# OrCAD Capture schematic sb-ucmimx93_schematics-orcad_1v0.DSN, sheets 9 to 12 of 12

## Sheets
9 11 Power: size A3; title: SB-UCMIMX93    08. Power
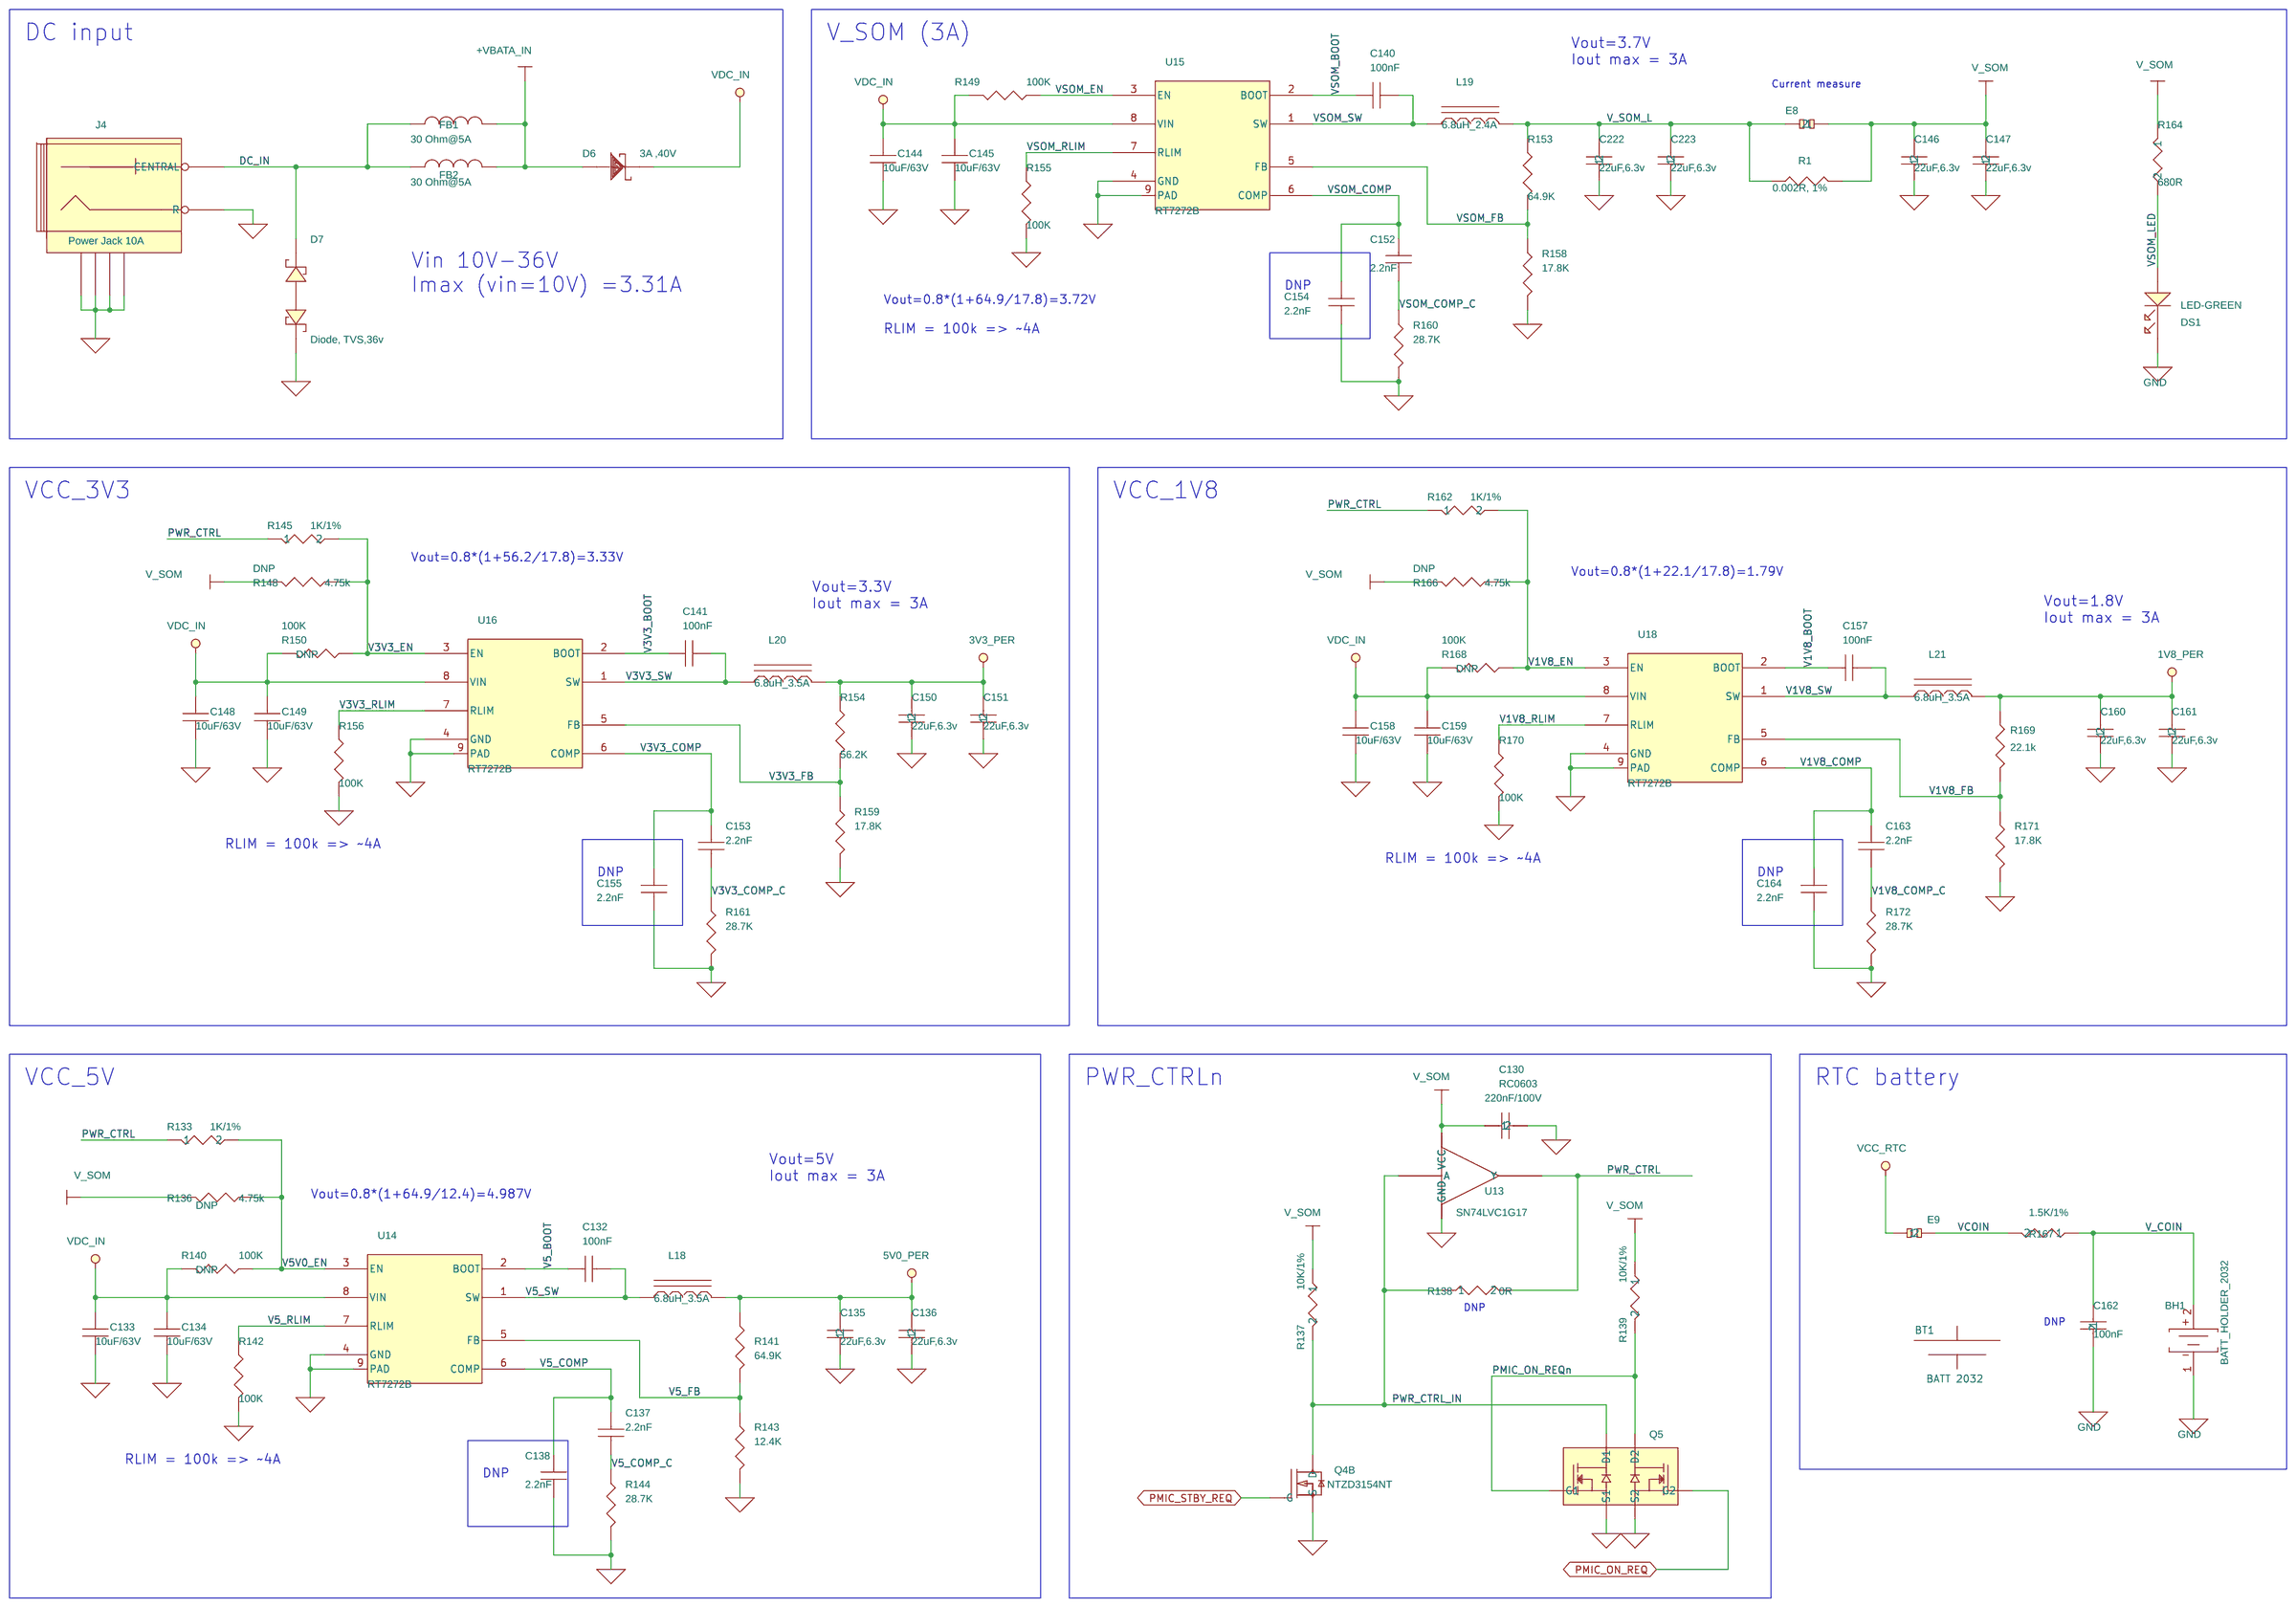
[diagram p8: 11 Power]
10 03 Ethernet and Expansion conn.: size A3; title: SB-UCMIMX93      03. Ethernet and Expansion connectors
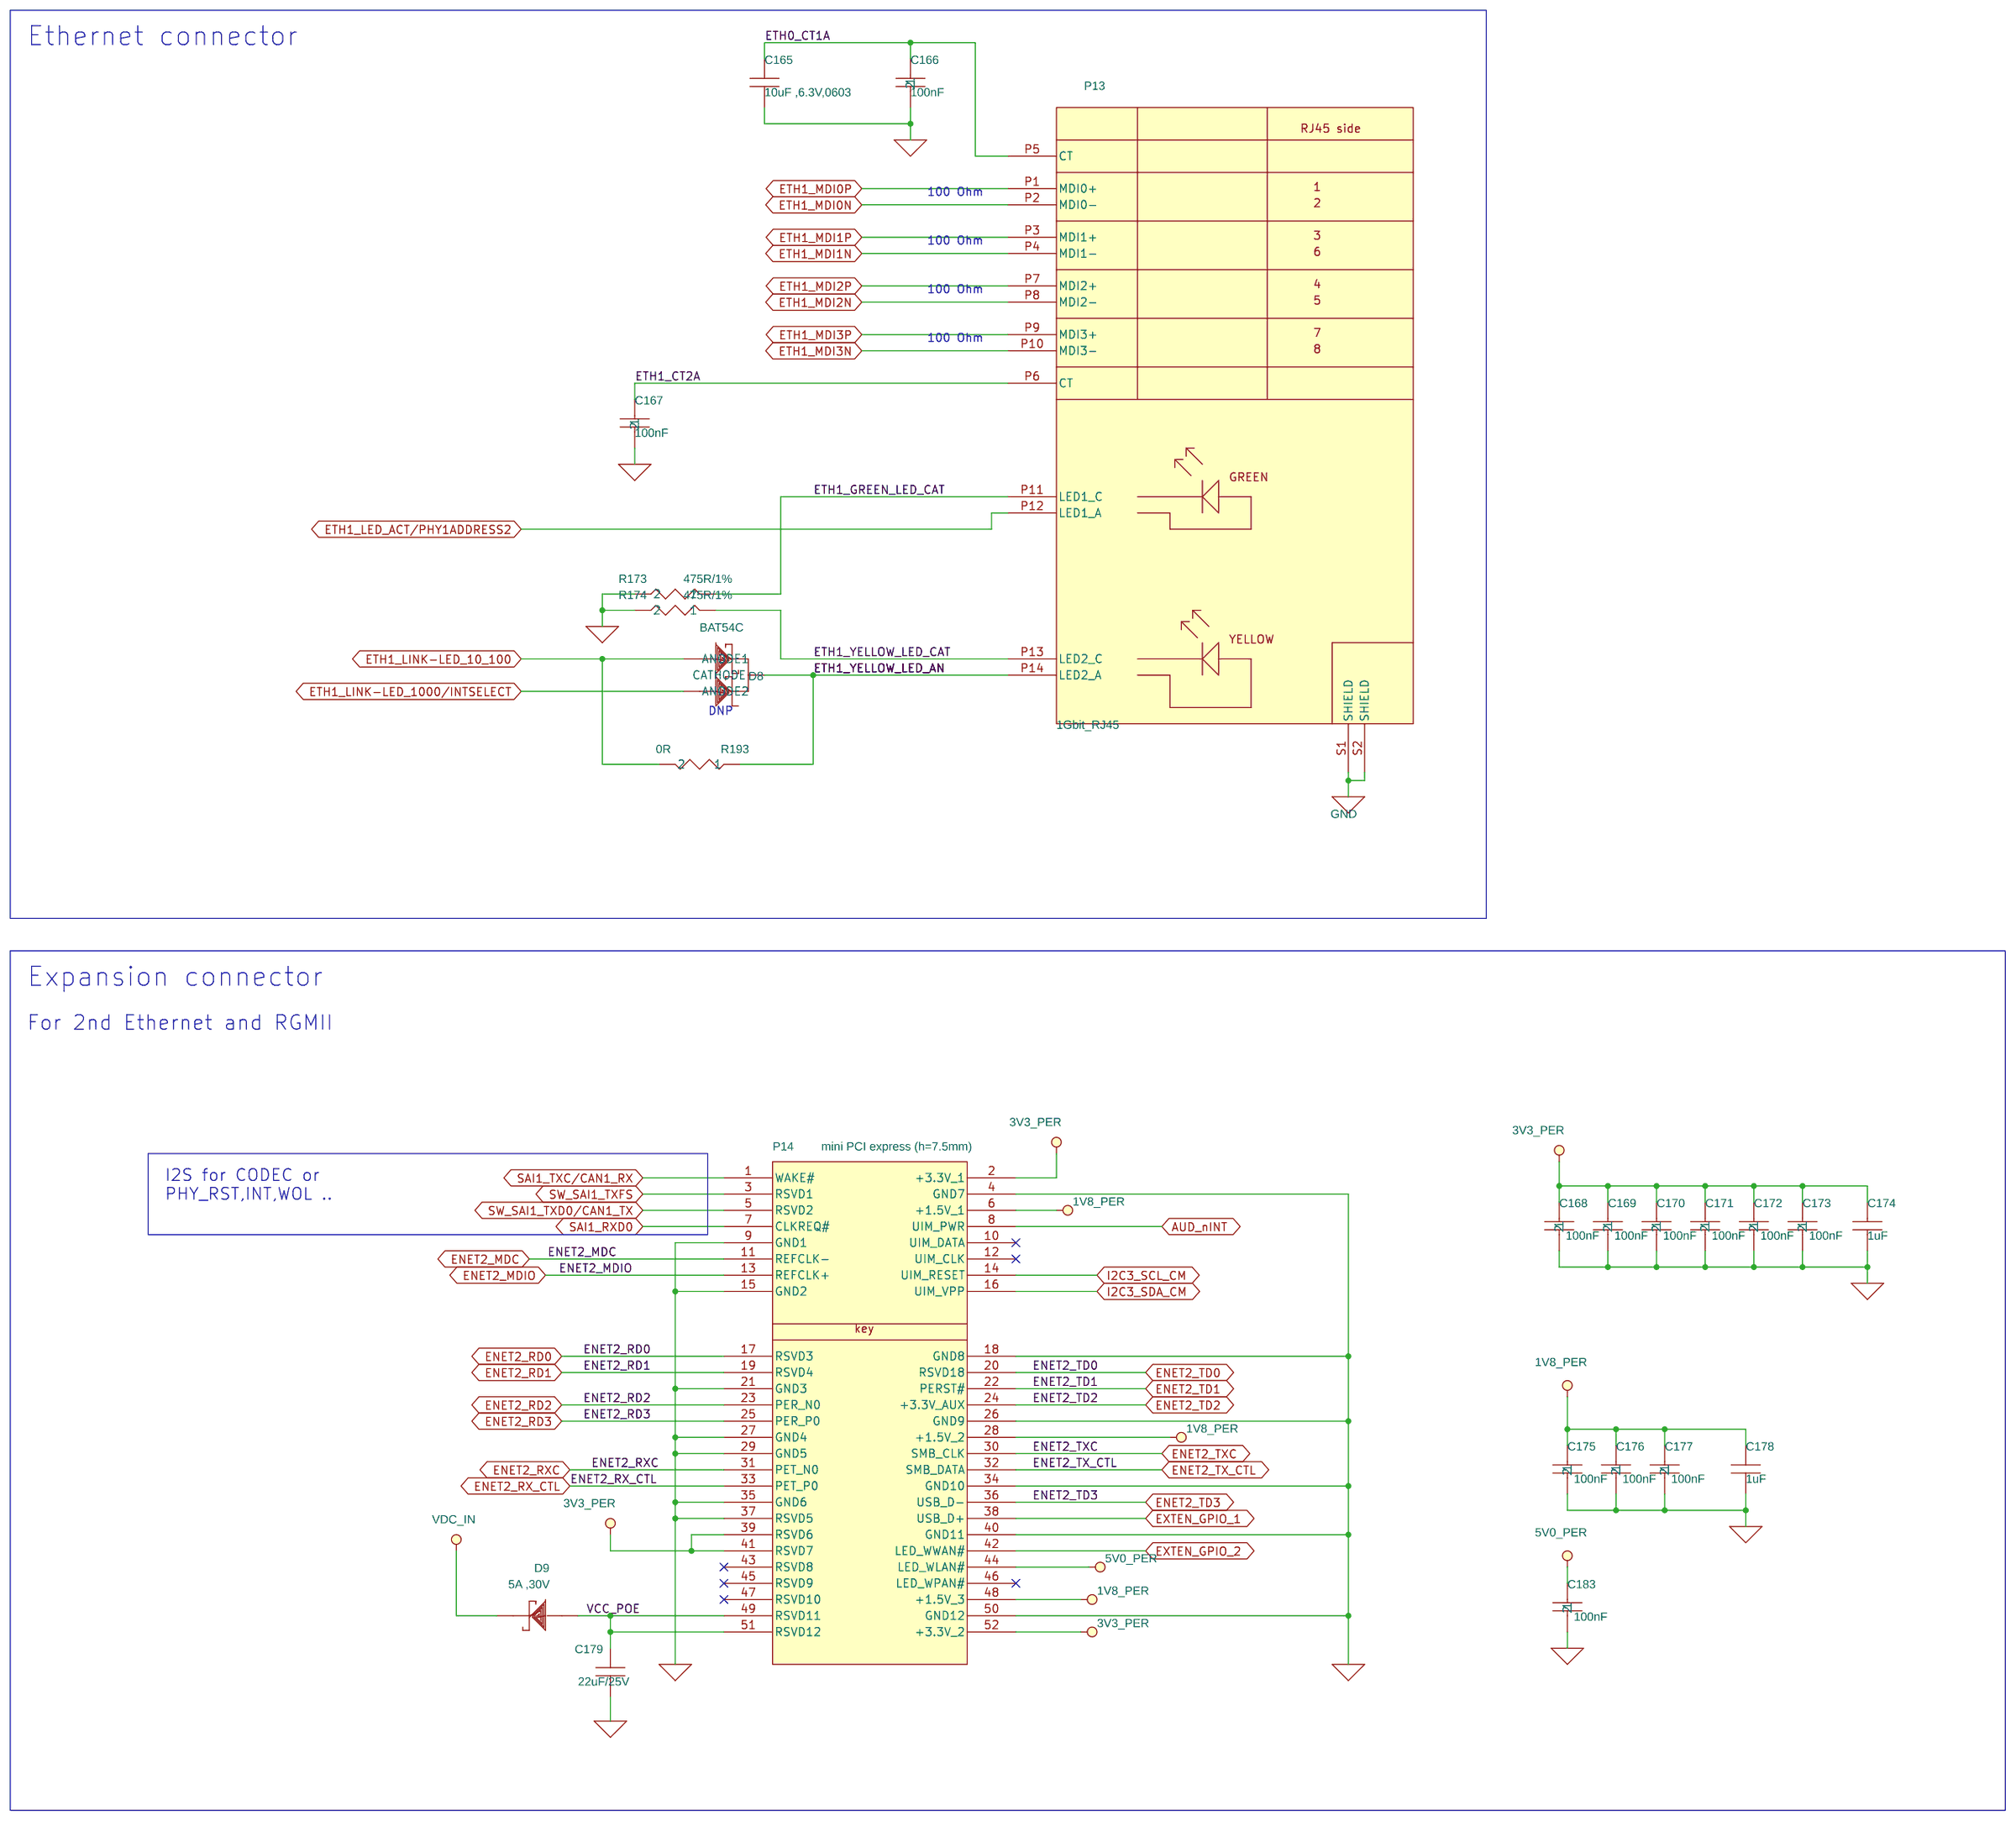
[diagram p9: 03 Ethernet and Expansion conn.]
11 10 Console, RS232, SD, miniPCIe: size A3; title: SB-UCMIMX93      10. Console, RS232, SD, miniPCIe
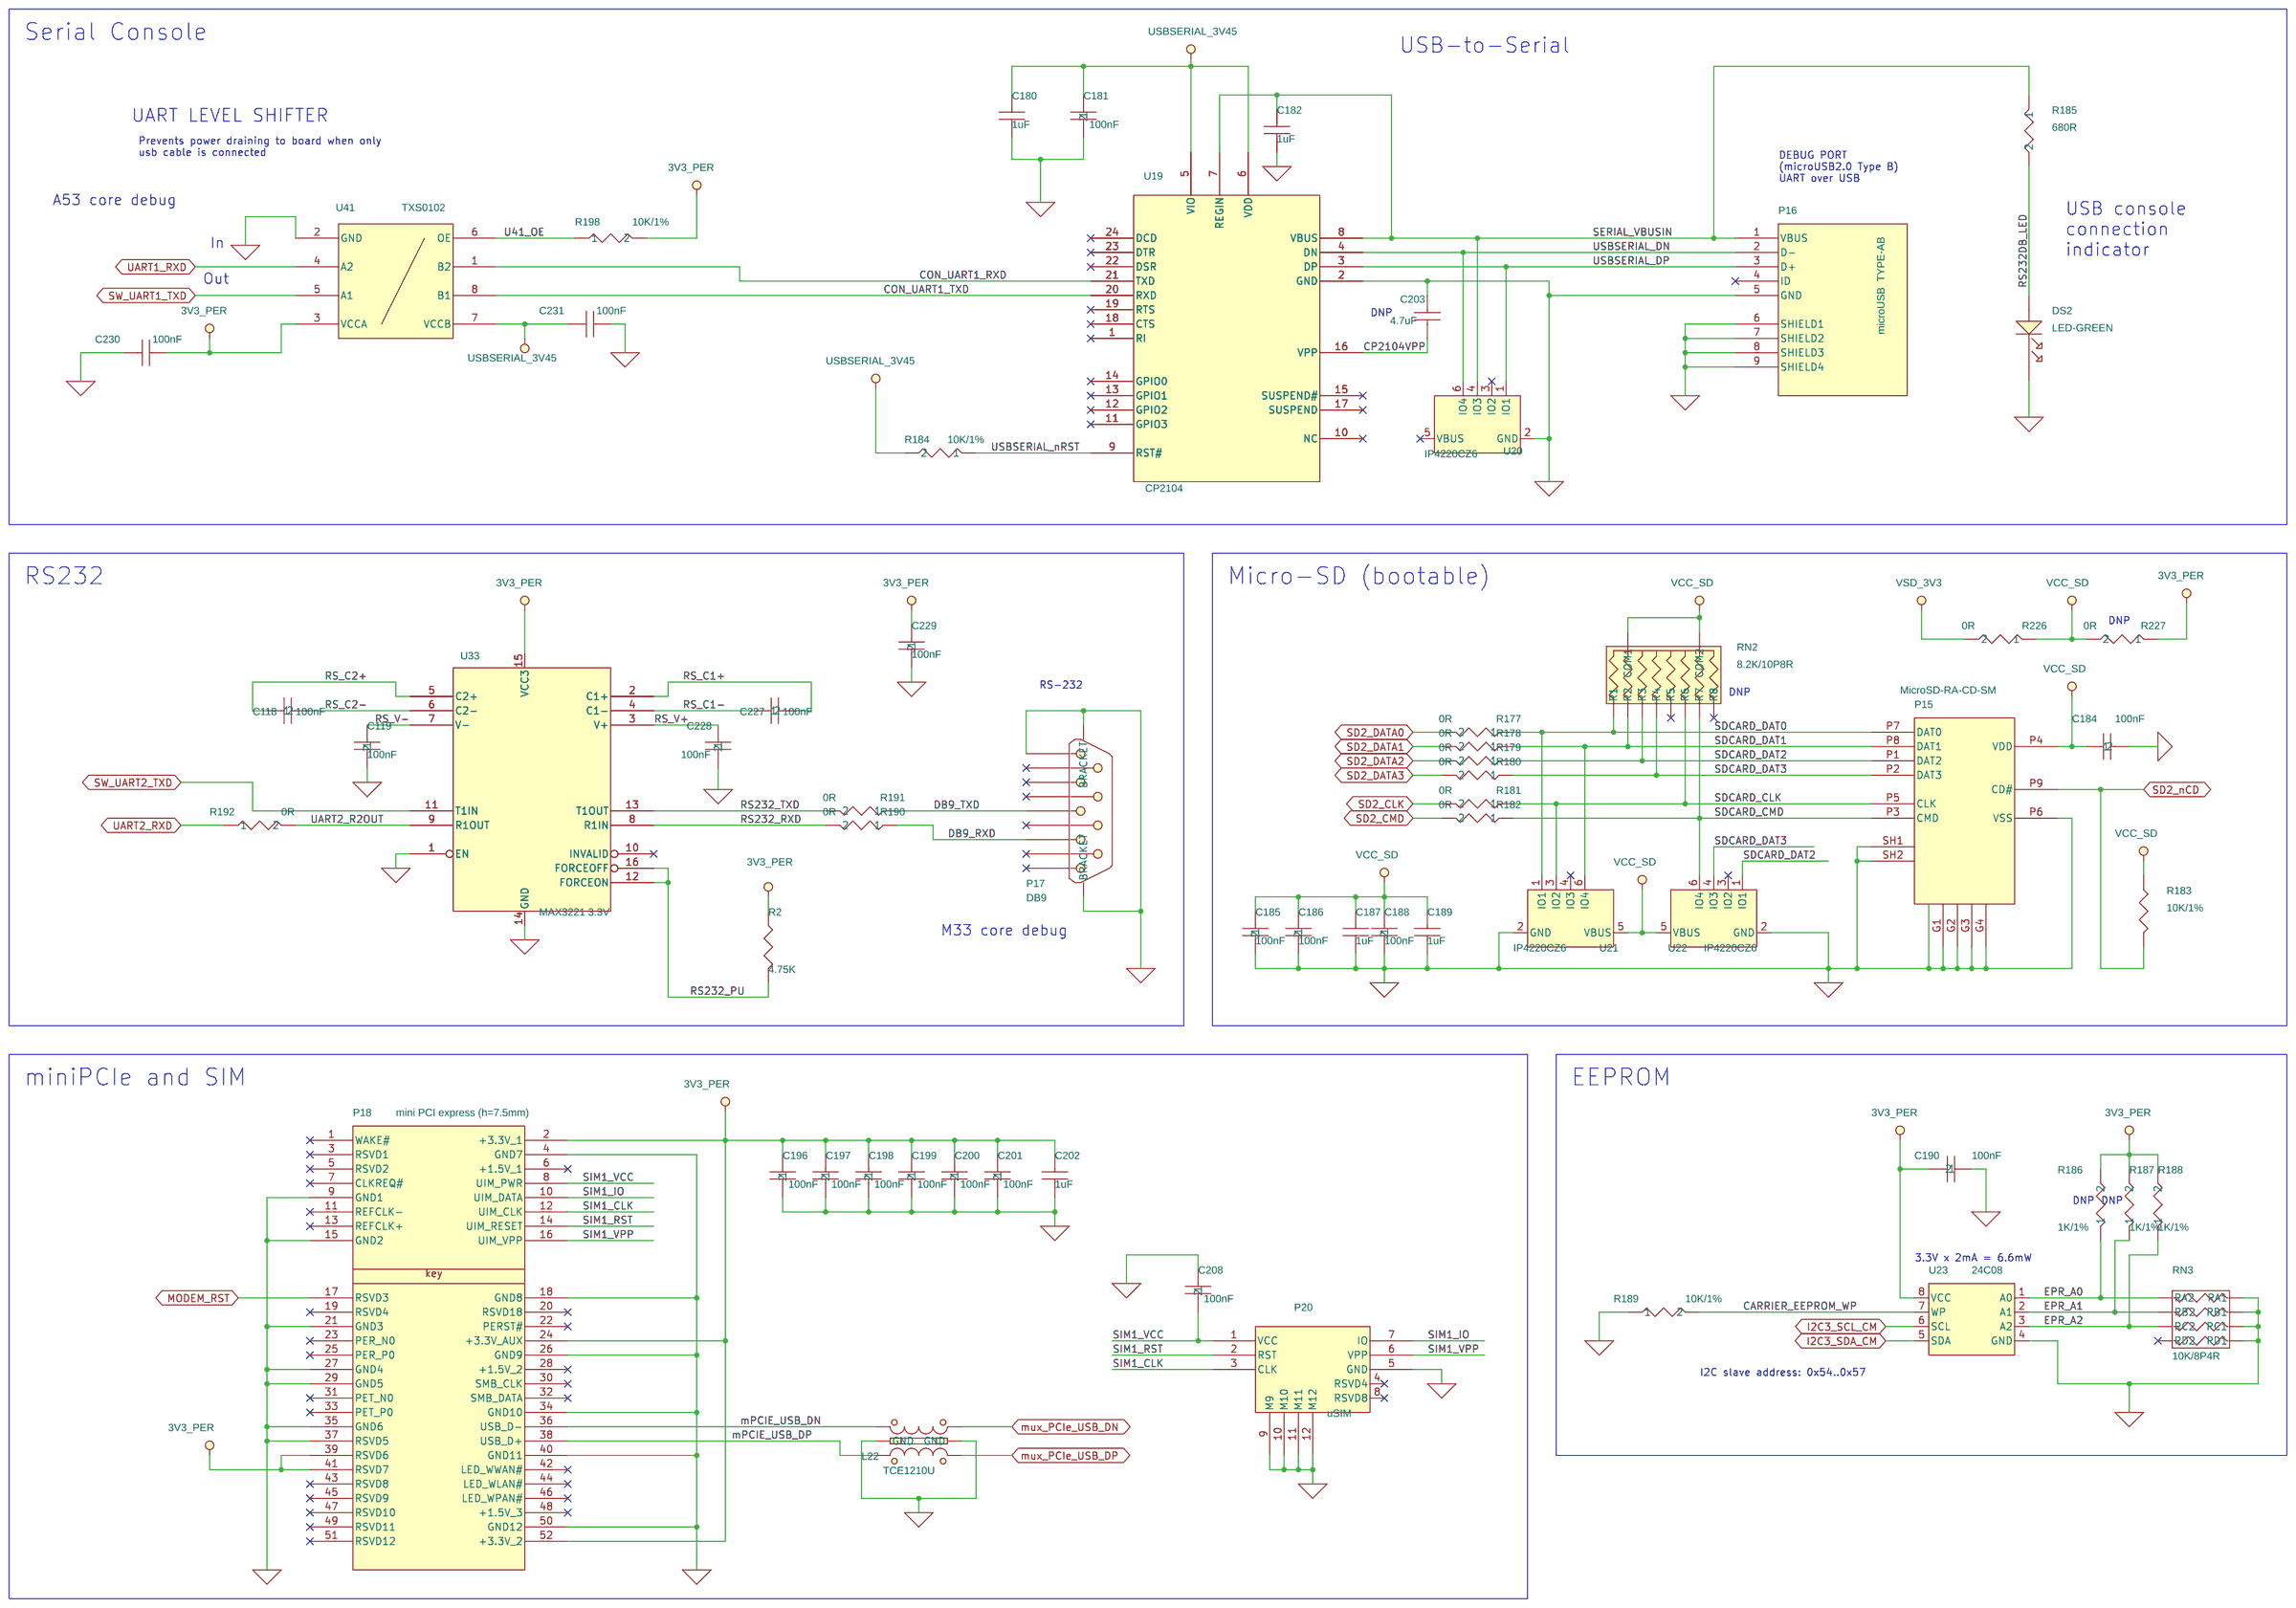
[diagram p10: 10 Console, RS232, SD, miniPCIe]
12 04 USB1: size A3; title: SB-UCMIMX93    04. USB1
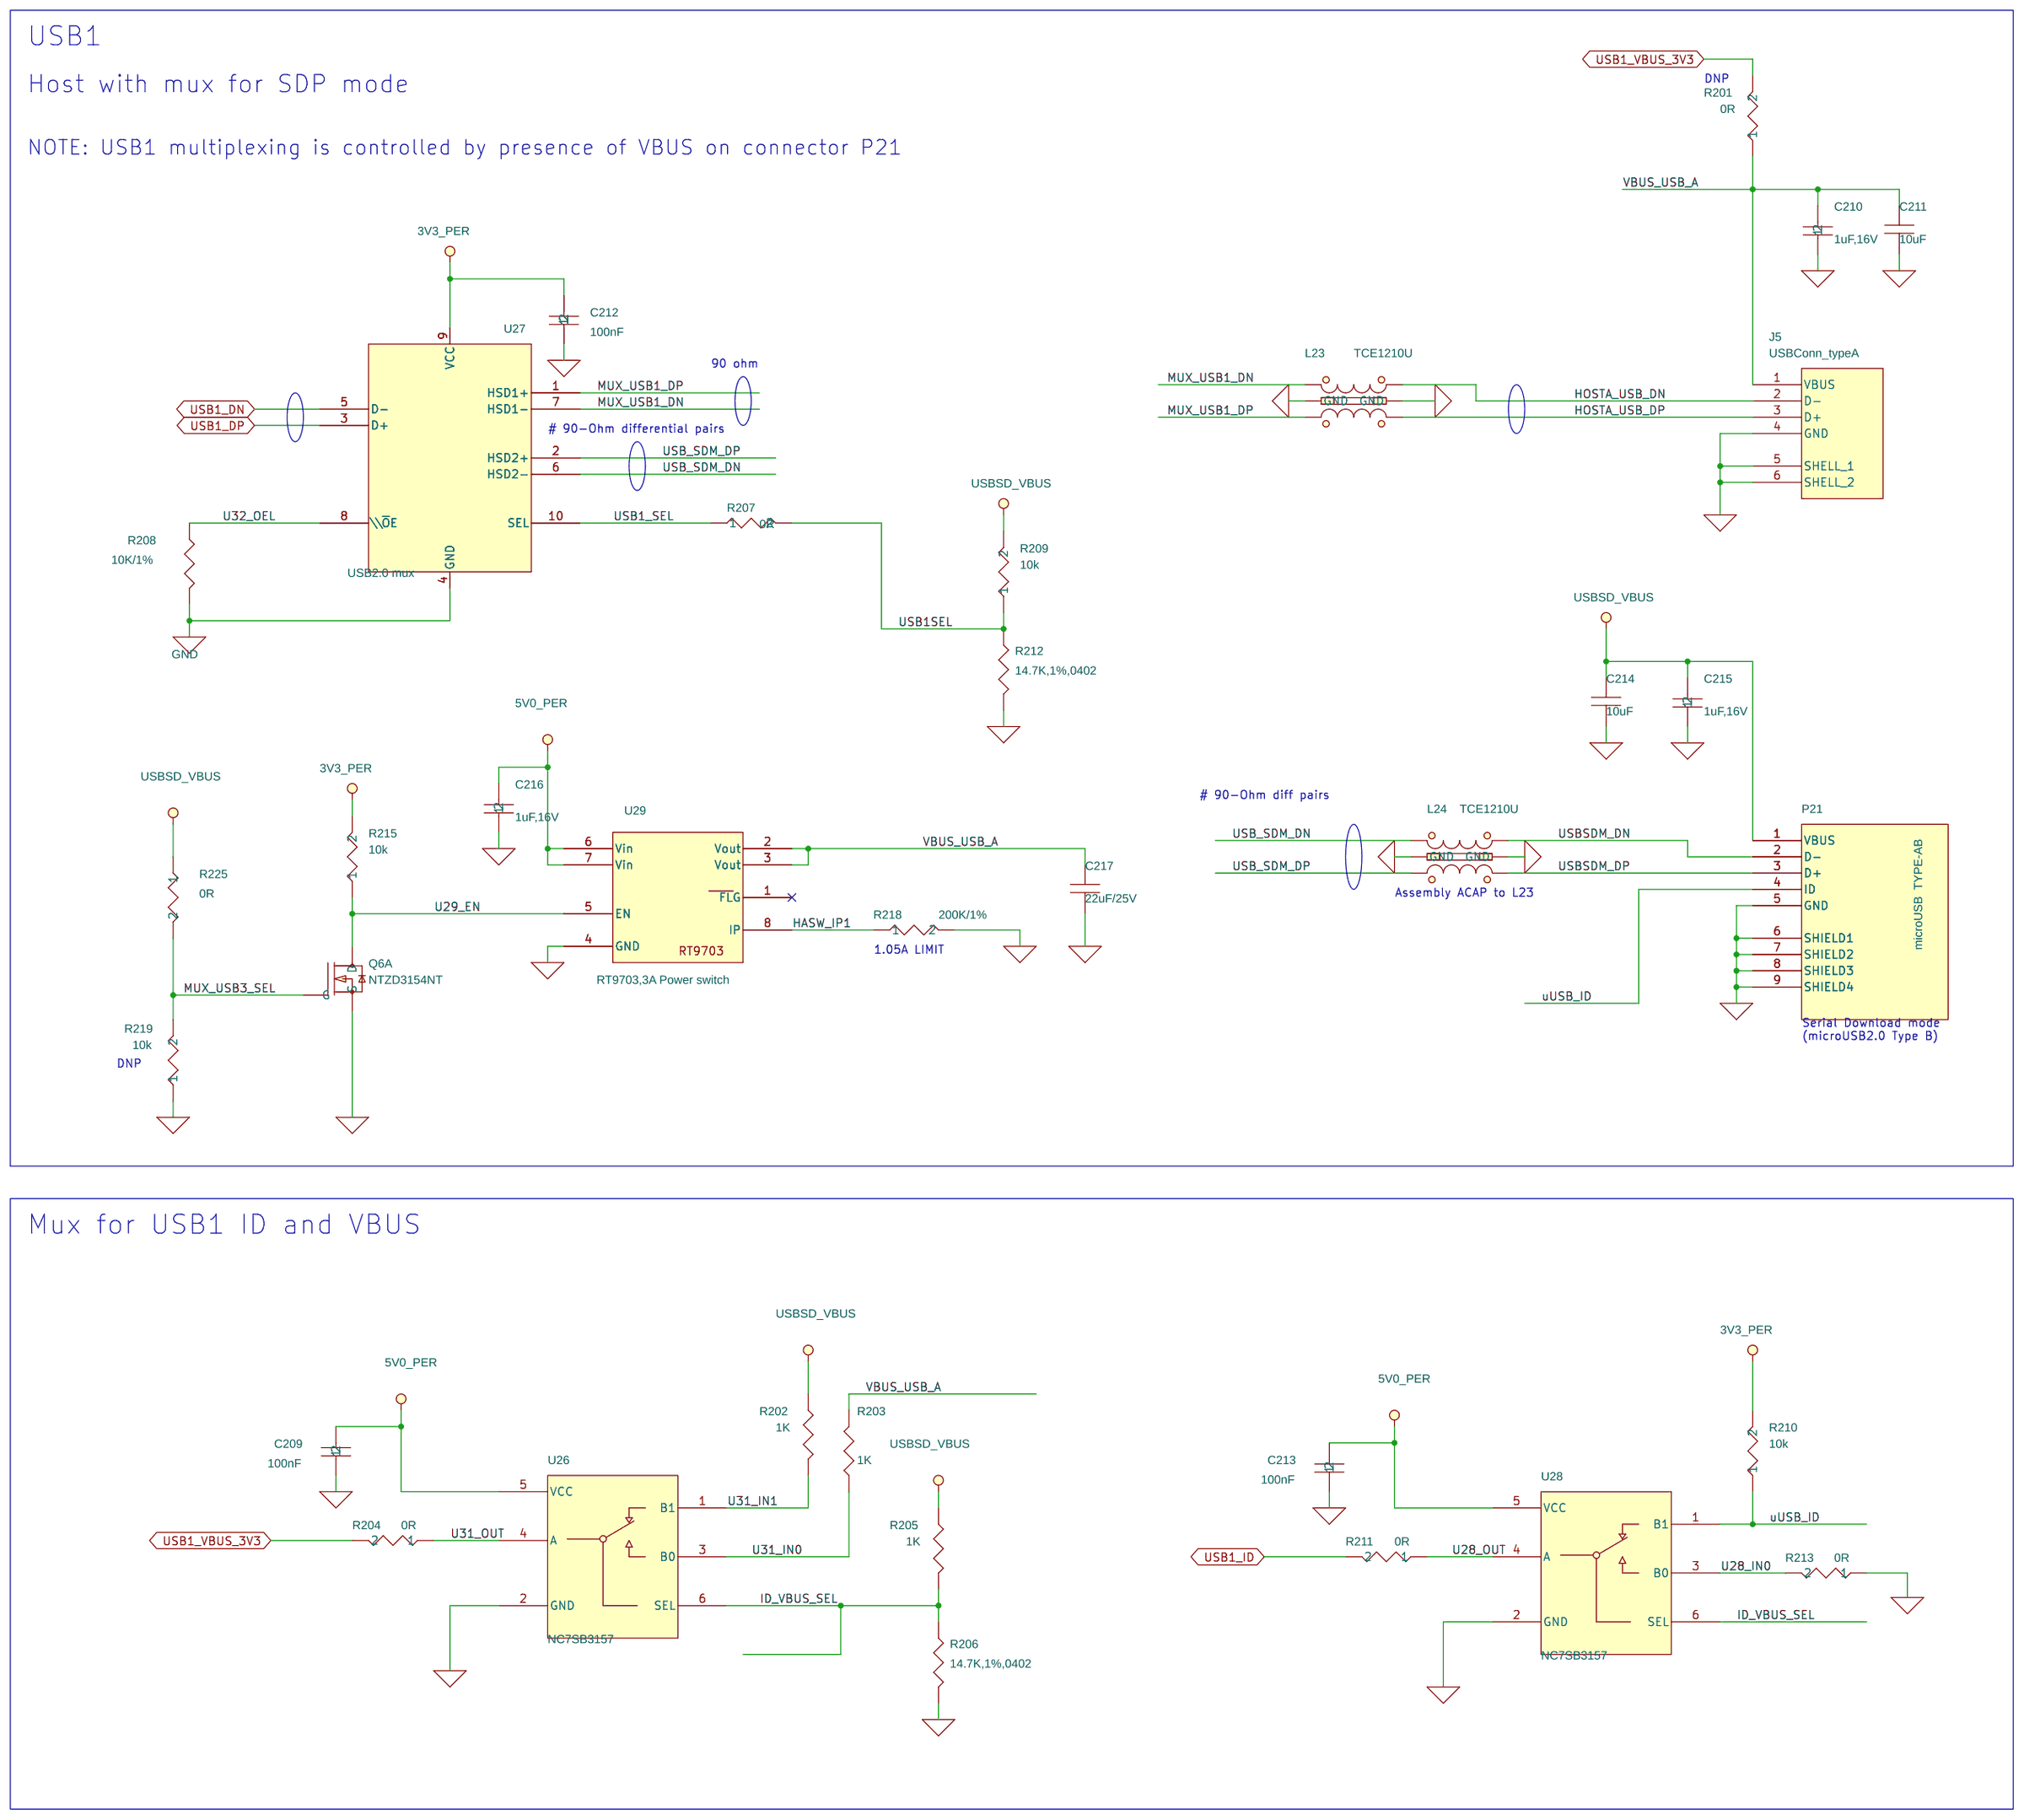
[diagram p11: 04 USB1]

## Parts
sheet 03 Ethernet and Expansion conn.
C165  10uF ,6.3V,0603  [RC0603]
C166  100nF  [RC0402]
C167  100nF  [RC0402]
C168  100nF  [RC0402]
C169  100nF  [RC0402]
C170  100nF  [RC0402]
C171  100nF  [RC0402]
C172  100nF  [RC0402]
C173  100nF  [RC0402]
C174  1uF  [RC0402]
C175  100nF  [RC0402]
C176  100nF  [RC0402]
C177  100nF  [RC0402]
C178  1uF  [RC0402]
C179  22uF/25V  [C0805]
C183  100nF  [RC0402]
D8  BAT54C  [SOT23]
D9  5A ,30V  [SOD-128]
P13  1Gbit_RJ45  [DUSBRJ-1G]
P14  mini PCI express (h=7.5mm)  [MINIPCIE-4]
R173  475R/1%  [RC0402]
R174  475R/1%  [RC0402]
R193  0R  [RC0402]
sheet 04 USB1
C209  100nF  [RC0402]
C210  1uF,16V  [RC0402]
C211  10uF  [C0603-08]
C212  100nF  [RC0402]
C213  100nF  [RC0402]
C214  10uF  [C0603-08]
C215  1uF,16V  [RC0402]
C216  1uF,16V  [RC0402]
C217  22uF/25V  [C0805]
J5  USBConn_typeA  [USB-A-SM]
L23  TCE1210U  [EMI1012-ESD]
L24  TCE1210U  [EMI1012-ESD]
P21  microUSB  TYPE-AB  [MICRO-USB-AB-RA-SM]
Q6  NTZD3154NT  [SOT-563-6]  (section A)
R201  0R  [RC0402]
R202  1K  [RC0402]
R203  1K  [RC0402]
R204  0R  [RC0402]
R205  1K  [RC0402]
R206  14.7K,1%,0402  [RC0402]
R207  0R  [RC0402]
R208  10K/1%  [RC0402]
R209  10k  [RC0402]
R210  10k  [RC0402]
R211  0R  [RC0402]
R212  14.7K,1%,0402  [RC0402]
R213  0R  [RC0402]
R215  10k  [RC0402]
R218  200K/1%  [RC0402]
R219  10k  [RC0402]
R225  0R  [RC0402]
U26  NC7SB3157  [SC70-6]
U27  USB2.0 mux  [MO-255U1418E]
U28  NC7SB3157  [SC70-6]
U29  RT9703,3A Power switch  [SO8-150]
sheet 10 Console, RS232, SD, miniPCIe
C118  100nF  [RC0402]
C119  100nF  [RC0402]
C180  1uF  [RC0402]
C181  100nF  [RC0402]
C182  1uF  [RC0402]
C184  100nF  [RC0402]
C185  100nF  [RC0402]
C186  100nF  [RC0402]
C187  1uF  [RC0402]
C188  100nF  [RC0402]
C189  1uF  [RC0402]
C190  100nF  [RC0402]
C196  100nF  [RC0402]
C197  100nF  [RC0402]
C198  100nF  [RC0402]
C199  100nF  [RC0402]
C200  100nF  [RC0402]
C201  100nF  [RC0402]
C202  1uF  [RC0402]
C203  4.7uF  [C0603-08]
C208  100nF  [RC0402]
C227  100nF  [RC0402]
C228  100nF  [RC0402]
C229  100nF  [RC0402]
C230  100nF  [RC0402]
C231  100nF  [RC0402]
DS2  LED-GREEN  [LED-1206]
L22  TCE1210U  [EMI1012-ESD]
P15  MicroSD-RA-CD-SM  [MicroSD-RA-CD-SM]
P16  microUSB  TYPE-AB  [MICRO-USB-AB-RA-SM]
P17  DB9  [DB9RATH]
P18  mini PCI express (h=7.5mm)  [MINIPCIE-4]
P20  uSIM  [SKT-MicroSIM6-SM]
R2  4.75K  [RC0402]
R177  0R  [RC0402]
R178  0R  [RC0402]
R179  0R  [RC0402]
R180  0R  [RC0402]
R181  0R  [RC0402]
R182  0R  [RC0402]
R183  10K/1%  [RC0402]
R184  10K/1%  [RC0402]
R185  680R  [RC0402]
R186  1K/1%  [RC0402]
R187  1K/1%  [RC0402]
R188  1K/1%  [RC0402]
R189  10K/1%  [RC0402]
R190  0R  [RC0402]
R191  0R  [RC0402]
R192  0R  [RC0402]
R198  10K/1%  [RC0402]
R226  0R  [RC0402]
R227  0R  [RC0402]
RN2  8.2K/10P8R  [RESNET10P1206]
RN3  10K/8P4R  [RESNET8P0805]
U19  CP2104  [MO-220VGGD-8]
U20  IP4220CZ6  [SOT23-6L-H1]
U21  IP4220CZ6  [SOT23-6L]
U22  IP4220CZ6  [SOT23-6L]
U23  24C08  [MO-229VCED-2]
U33  MAX3221 3.3V  [SSOP-16]
U41  TXS0102  [MO-187DA-8]
sheet 11 Power
BH1  BATT_HOLDER_2032  [BATTH20MM]
BT1  BATT 2032
C130  220nF/100V  [RC0603]
C132  100nF  [RC0402]
C133  10uF/63V  [C1210H2_5]
C134  10uF/63V  [C1210H2_5]
C135  22uF,6.3v  [RC0603]
C136  22uF,6.3v  [RC0603]
C137  2.2nF  [RC0402]
C138  2.2nF  [RC0402]
C140  100nF  [RC0402]
C141  100nF  [RC0402]
C144  10uF/63V  [C1210H2_5]
C145  10uF/63V  [C1210H2_5]
C146  22uF,6.3v  [RC0603]
C147  22uF,6.3v  [RC0603]
C148  10uF/63V  [C1210H2_5]
C149  10uF/63V  [C1210H2_5]
C150  22uF,6.3v  [RC0603]
C151  22uF,6.3v  [RC0603]
C152  2.2nF  [RC0402]
C153  2.2nF  [RC0402]
C154  2.2nF  [RC0402]
C155  2.2nF  [RC0402]
C157  100nF  [RC0402]
C158  10uF/63V  [C1210H2_5]
C159  10uF/63V  [C1210H2_5]
C160  22uF,6.3v  [RC0603]
C161  22uF,6.3v  [RC0603]
C162  100nF  [RC0402]
C163  2.2nF  [RC0402]
C164  2.2nF  [RC0402]
C222  22uF,6.3v  [RC0603]
C223  22uF,6.3v  [RC0603]
D6  3A ,40V  [DO-214AC]
D7  Diode, TVS,36v  [SOD-323]
DS1  LED-GREEN  [LED-1206]
E8  HDR1X2  [1X2THHDR]
E9  HDR1X2  [1X2THHDR]
FB1  30 Ohm@5A  [FB0603]
FB2  30 Ohm@5A  [FB0603]
J4  Power Jack 10A  [PJ-0810-TH]
L18  6.8uH_3.5A  [IND6x5_5x3]
L19  6.8uH_2.4A  [IND6x5_5x3]
L20  6.8uH_3.5A  [IND6x5_5x3]
L21  6.8uH_3.5A  [IND6x5_5x3]
Q4  NTZD3154NT  [SOT-563-6]  (sections A,B)
Q5  0.5A,20V,Vgs max 6V  [SOT-563-6]
R1  0.002R, 1%  [R1206]
R133  1K/1%  [RC0402]
R136  4.75k  [RC0402]
R137  10K/1%  [RC0402]
R138  0R  [RC0402]
R139  10K/1%  [RC0402]
R140  100K  [RC0402]
R141  64.9K  [RC0402]
R142  100K  [RC0402]
R143  12.4K  [RC0402]
R144  28.7K  [RC0402]
R145  1K/1%  [RC0402]
R148  4.75k  [RC0402]
R149  100K  [RC0402]
R150  100K  [RC0402]
R153  64.9K  [RC0402]
R154  56.2K  [RC0402]
R155  100K  [RC0402]
R156  100K  [RC0402]
R158  17.8K  [RC0402]
R159  17.8K  [RC0402]
R160  28.7K  [RC0402]
R161  28.7K  [RC0402]
R162  1K/1%  [RC0402]
R164  680R  [RC0402]
R166  4.75k  [RC0402]
R167  1.5K/1%  [RC0402]
R168  100K  [RC0402]
R169  22.1k  [RC0402]
R170  100K  [RC0402]
R171  17.8K  [RC0402]
R172  28.7K  [RC0402]
U13  SN74LVC1G17
U14  RT7272B  [PSOP-8-2X2]
U15  RT7272B  [PSOP-8-2X2]
U16  RT7272B  [PSOP-8-2X2]
U18  RT7272B  [PSOP-8-2X2]

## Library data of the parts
C165 = Cap.,10uF,6.3V,0603,X5R: CLABCONF0: =SB-UCMIMX93
C166 C186 = 100nF,_10V,_X7R,_10%,_0402_9: CLABCONF0: =SB-UCMIMX93
C167 C228 = 100nF,_10V,_X7R,_10%,_0402_4: CLABCONF0: =SB-UCMIMX93
C168 C184 = 100nF,_10V,_X7R,_10%,_0402_1: CLABCONF0: =SB-UCMIMX93
C119 C169 = 100nF,_10V,_X7R,_10%,_0402_6: CLABCONF0: =SB-UCMIMX93
C170 C196 = 100nF,_10V,_X7R,_10%,_0402_10: CLABCONF0: =SB-UCMIMX93
C171 C199 = 100nF,_10V,_X7R,_10%,_0402_3: CLABCONF0: =SB-UCMIMX93
C172 C185 = 100nF,_10V,_X7R,_10%,_0402_8: CLABCONF0: =SB-UCMIMX93
C173 C190 = 100nF,_10V,_X7R,_10%,_0402: CLABCONF0: =SB-UCMIMX93
C174 C178 C180 C182 C187 C189 C202 = 1uF,X5R,6.3V,0402: CLABCONF0: =SB-UCMIMX93
C175 C181 = 100nF,_10V,_X7R,_10%,_0402_2: CLABCONF0: =SB-UCMIMX93
C176 C200 = 100nF,_10V,_X7R,_10%,_0402_5: CLABCONF0: =SB-UCMIMX93
C177 C188 = 100nF,_10V,_X7R,_10%,_0402_7: CLABCONF0: =SB-UCMIMX93
C179 = Cap.,22uF,25V,_0805: CLABCONF0: =SB-UCMIMX93
C183 C229 = 100nF,_10V,_X7R,_10%,_0402_11: CLABCONF0: =SB-UCMIMX93
D8 = BAT54C: CLABCONF0: DNP
D9 = Diode_Shotky,5A,30V: CLABCONF0: =SB-UCMIMX93
P13 = Con_0.,1GBit_RJ45,_short: CLABCONF0: =SB-UCMIMX93
P14 P18 = mini_PCIe_0: CLABCONF0: =SB-UCMIMX93; P/N: 182K05202S
R173 = 475R_1%,_0402_1: CLABCONF0: =SB-UCMIMX93
R174 = 475R_1%,_0402: CLABCONF0: =SB-UCMIMX93
R181 R193 R213 = 0R,_0402_1: CLABCONF0: =SB-UCMIMX93
C209 = 100nF,_10V,_X7R,_10%,_0402: CLABCONF0: =SB-UCMIMX93; Group: LAN2
C210 = 100nF,_10V,_X7R,_10%,_0402_3: CLABCONF0: =SB-UCMIMX93; P/N: 151C10500S
C211 C214 = 10uF,6_0.3V,0603,20%X5R: CLABCONF0: =SB-UCMIMX93
C212 = 100nF,_10V,_X7R,_10%,_0402_2: CLABCONF0: =SB-UCMIMX93; Group: LAN2
C213 = 100nF,_10V,_X7R,_10%,_0402_5: CLABCONF0: =SB-UCMIMX93; Group: LAN2
C215 = 100nF,_10V,_X7R,_10%,_0402_4: CLABCONF0: =SB-UCMIMX93; P/N: 151C10500S
C216 = 100nF,_10V,_X7R,_10%,_0402_1: CLABCONF0: =SB-UCMIMX93; P/N: 151C10500S
C217 = 22uF,25V,_0805: CLABCONF0: =SB-UCMIMX93
J5 = USB_Conn.,_Fem,_Type_A_,_TH,_RA: CLABCONF0: =SB-UCMIMX93
L22-L24 = ESD_CHOKE_DIFFx2_10: CLABCONF0: =SB-UCMIMX93; P/N: 142D11801S
P16 P21 = Conn.,_Micro-USB,_B-Type: CLABCONF0: =SB-UCMIMX93; P/N: 180K00501S
Q4 Q6 = N-MOSFET_Dual: CLABCONF0: =SB-UCMIMX93; P/N: 131D31540S
R138 R201 = 0R,_0402: CLABCONF0: DNP
R202 R203 R205 = RESISTOR: CLABCONF0: =SB-UCMIMX93; P/N: 161C10011S
R204 = 0R,_0402_2: CLABCONF0: =SB-UCMIMX93
R206 R212 = RESISTOR: CLABCONF0: =SB-UCMIMX93; P/N: 161C14721S
R207 = 0R,_0402_4: CLABCONF0: =SB-UCMIMX93
R208 = 10K,1%,0402,1_16W_0: CLABCONF0: =SB-UCMIMX93
R209 = 1M_,5%,_0402_2: CLABCONF0: =SB-UCMIMX93; P/N: 161C10021S
R210 = 1M_,5%,_0402_1: CLABCONF0: =SB-UCMIMX93; P/N: 161C10021S
R211 = 0R,_0402_5: CLABCONF0: =SB-UCMIMX93
R215 = 1M_,5%,_0402: CLABCONF0: =SB-UCMIMX93; P/N: 161C10021S
R218 = 100K,_1%,_0402,_1_16W: CLABCONF0: =SB-UCMIMX93; P/N: 161C20031S
R219 = 1M_,5%,_0402_3: CLABCONF0: DNP; P/N: 161C10021S
R225 = 0R,_0402_3: CLABCONF0: =SB-UCMIMX93
U26 U28 = Bus_switch_2_1: CLABCONF0: =SB-UCMIMX93
U27 = USB2_0.0_mux: CLABCONF0: =SB-UCMIMX93; P/N: 116A72220S
U29 = RT9703,3A_Power_switch+FLG: CLABCONF0: =SB-UCMIMX93; P/N: 124S10080S
C118 = 100nF,_10V,_X7R,_10%,_0402_16: CLABCONF0: =SB-UCMIMX93
C197 = 100nF,_10V,_X7R,_10%,_0402_12: CLABCONF0: =SB-UCMIMX93
C198 = 100nF,_10V,_X7R,_10%,_0402_15: CLABCONF0: =SB-UCMIMX93
C201 = 100nF,_10V,_X7R,_10%,_0402_13: CLABCONF0: =SB-UCMIMX93
C203 = 4.7uF,_6.3V,_X5R,_20%,_0603: CLABCONF0: DNP; P/N: 151B10610S
C208 = 100nF,_10V,_X7R,_10%,_0402_17: CLABCONF0: =SB-UCMIMX93
C227 = 100nF,_10V,_X7R,_10%,_0402_14: CLABCONF0: =SB-UCMIMX93
C230 C231 = 100nF,_10V,_X7R,_10%,_0402_0: CLABCONF0: =SB-UCMIMX93
DS1 DS2 = LED-GREEN_1206_2: CLABCONF0: =SB-UCMIMX93
P15 = microSD_push-pull: CLABCONF0: =SB-UCMIMX93; P/N: 182K01300S
P17 = DB9_RA_TH_Male_ATX: CLABCONF0: =SB-UCMIMX93
P20 = uSIM_SOCKET_0: CLABCONF0: =SB-UCMIMX93
R2 = 10K,1%,0402,1_16W_0: CLABCONF0: =SB-UCMIMX93; Group: Always; P/N: 161C47511S
R177 = 0R,_0402_1_3: CLABCONF0: =SB-UCMIMX93
R178 = 0R,_0402_1_6: CLABCONF0: =SB-UCMIMX93
R179 = 0R,_0402_1_5: CLABCONF0: =SB-UCMIMX93
R180 = 0R,_0402_1_2: CLABCONF0: =SB-UCMIMX93
R182 = 0R,_0402_1_7: CLABCONF0: =SB-UCMIMX93
R183 = 10K,1%,0402,1_16W_0_1: CLABCONF0: =SB-UCMIMX93
R184 = 10K,1%,0402,1_16W_2: CLABCONF0: =SB-UCMIMX93
R164 R185 = 47K,_0402: CLABCONF0: =SB-UCMIMX93; P/N: 161C68001S
R186 = 1K,1%,0402,1_16W_1: CLABCONF0: DNP; Group: CAN
R187 = 1K,1%,0402,1_16W: CLABCONF0: DNP; Group: CAN
R162 R188 = 1K,1%,0402,1_16W_2: CLABCONF0: =SB-UCMIMX93; Group: CAN
R137 R189 = 10K,1%,0402,1_16W_1: CLABCONF0: =SB-UCMIMX93
R190 = 0R,_0402_1_4: CLABCONF0: =SB-UCMIMX93
R191 = 0R,_0402_1_1: CLABCONF0: =SB-UCMIMX93
R192 = 0R,_0402: CLABCONF0: =SB-UCMIMX93
R139 R198 = 10K,1%,0402,1_16W: CLABCONF0: =SB-UCMIMX93
R226 = 0R,_0402_0: CLABCONF0: =SB-UCMIMX93; P/N: 161C00005S
R227 = 0R,_0402_0_1: CLABCONF0: DNP; P/N: 161C00005S
RN2 = RN,8.2K,10P8R@1206: CLABCONF0: DNP
RN3 = RN,10K,8P4R@0805: CLABCONF0: =SB-UCMIMX93
U19 = CP2104_0: CLABCONF0: =SB-UCMIMX93; P/N: 116A00140S
U20-U22 = IP4220CZ6_0: CLABCONF0: =SB-UCMIMX93
U23 = 24C02,_serial_EE,_2KB,_I2C: CLABCONF0: =SB-UCMIMX93; P/N: 111S31000S
U33 = MAX3221_RS-232_1T1R_3_2.3V_XCVR: CLABCONF0: =SB-UCMIMX93
U41 = TXS0102_0: CLABCONF0: =SB-UCMIMX93; P/N: 116A01020S
BH1 = BATT_HOLDER_0: CLABCONF0: =SB-UCMIMX93
BT1 = BATT_2032: CLABCONF0: =SB-UCMIMX93
C130 = 100nF,_10V,_X7R,_10%,_0402_1: CLABCONF0: =SB-UCMIMX93; P/N: 151E22410S
C132 C140 C141 C157 = 100nF,_10V,_X7R,_10%,_0402_0: CLABCONF0: =SB-UCMIMX93; Group: LAN2
C133 C134 C148 C149 C158 C159 = 22uF_25V: CLABCONF0: =SB-UCMIMX93; P/N: 151E10680S
C135 = 100nF,_10V,_X7R,_10%,_0402_11: CLABCONF0: =SB-UCMIMX93; P/N: 151B22610S
C136 = 100nF,_10V,_X7R,_10%,_0402_4: CLABCONF0: =SB-UCMIMX93; P/N: 151B22610S
C137 = 2.2nF,_50V,_X7R,_10%,_0402_5: CLABCONF0: =SB-UCMIMX93
C138 = 2.2nF,_50V,_X7R,_10%,_0402_2: CLABCONF0: DNP
C144 C145 = 22uF_25V: CLABCONF0: =SB-UCMIMX93; P/N: 151D10630S
C146 = 100nF,_10V,_X7R,_10%,_0402_2: CLABCONF0: =SB-UCMIMX93; P/N: 151B22610S
C147 = 100nF,_10V,_X7R,_10%,_0402_3: CLABCONF0: =SB-UCMIMX93; P/N: 151B22610S
C150 = 100nF,_10V,_X7R,_10%,_0402_10: CLABCONF0: =SB-UCMIMX93; P/N: 151B22610S
C151 = 100nF,_10V,_X7R,_10%,_0402: CLABCONF0: =SB-UCMIMX93; P/N: 151B22610S
C152 = 2.2nF,_50V,_X7R,_10%,_0402_4: CLABCONF0: =SB-UCMIMX93
C153 = 2.2nF,_50V,_X7R,_10%,_0402_1: CLABCONF0: =SB-UCMIMX93
C154 = 2.2nF,_50V,_X7R,_10%,_0402: CLABCONF0: DNP
C155 = 2.2nF,_50V,_X7R,_10%,_0402_7: CLABCONF0: DNP
C160 = 100nF,_10V,_X7R,_10%,_0402_9: CLABCONF0: =SB-UCMIMX93; P/N: 151B22610S
C161 = 100nF,_10V,_X7R,_10%,_0402_8: CLABCONF0: =SB-UCMIMX93; P/N: 151B22610S
C162 = 100nF,_10V,_X7R,_10%,_0402_7: CLABCONF0: DNP; P/N: 151B10400S
C163 = 2.2nF,_50V,_X7R,_10%,_0402_6: CLABCONF0: =SB-UCMIMX93
C164 = 2.2nF,_50V,_X7R,_10%,_0402_3: CLABCONF0: DNP
C222 = 100nF,_10V,_X7R,_10%,_0402_6: CLABCONF0: =SB-UCMIMX93; P/N: 151B22610S
C223 = 100nF,_10V,_X7R,_10%,_0402_5: CLABCONF0: =SB-UCMIMX93; P/N: 151B22610S
D6 = Diode_Shotky,5A,30V_0: CLABCONF0: =SB-UCMIMX93; P/N: 130E40001S
D7 = 1A_Schottky_Barrier_Rectifier_1: CLABCONF0: =SB-UCMIMX93; P/N: 132D10080S
E8 = HDR_1x2_100MIL_TH_JUMPER: CLABCONF0: =SB-UCMIMX93
E9 = HDR_1x2_100MIL_TH_JUMPER_1: CLABCONF0: =SB-UCMIMX93
FB1 = Ferrite_bead_,_30_Ohm@5A_1: CLABCONF0: =SB-UCMIMX93
FB2 = Ferrite_bead_,_30_Ohm@5A: CLABCONF0: =SB-UCMIMX93
J4 = DC_Jack_,5.5_2.5,10A,20V: CLABCONF0: =SB-UCMIMX93
L18 L20 L21 = IND_6.8uH_3.5A: CLABCONF0: =SB-UCMIMX93; P/N: 147A6R802S
L19 = IND_6.8uH_3.5A: CLABCONF0: =SB-UCMIMX93; P/N: 147A6R804S
Q5 = DUAL_N-MOSFET,_0.5A_20V: CLABCONF0: =SB-UCMIMX93
R1 = RESISTOR: CLABCONF0: =SB-UCMIMX93; P/N: 161F00211S
R133 = 1K,1%,0402,1_16W: CLABCONF0: =SB-UCMIMX93; Group: CAN
R136 R148 R166 = 100K,_0402_0: CLABCONF0: DNP; P/N: 161C47511S
R140 R150 R168 = 100K,_0402_0: CLABCONF0: DNP
R141 R153 = 10.5K_1%,0402: CLABCONF0: =SB-UCMIMX93; P/N: 161C64921S
R142 R149 R155 R156 R170 = 100K,_0402_0: CLABCONF0: =SB-UCMIMX93
R143 = 2.37K_1%,_0402: CLABCONF0: =SB-UCMIMX93; P/N: 161C12421S
R144 R160 R161 R172 = 40.2k_1%: CLABCONF0: =SB-UCMIMX93; P/N: 161C28721S
R145 = 1K,1%,0402,1_16W_1: CLABCONF0: =SB-UCMIMX93; Group: CAN
R154 = 10.5K_1%,0402: CLABCONF0: =SB-UCMIMX93; P/N: 161C56221S
R158 R159 R171 = 2.37K_1%,_0402: CLABCONF0: =SB-UCMIMX93; P/N: 161C17821S
R167 = 1.5K_1%,_0402: CLABCONF0: =SB-UCMIMX93
R169 = RESISTOR: CLABCONF0: =SB-UCMIMX93; P/N: 161C22121S
U13 = SN74LVC1G17: CLABCONF0: =SB-UCMIMX93; P/N: 106D90000S
U14-U16 U18 = RT7272B,Converter,3A,36V: CLABCONF0: =SB-UCMIMX93; P/N: 123V30000S

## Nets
1V8_PER: C160.2 C161.2 C175.1 C176.1 C177.1 C178.1 L21.2 P14.6(+1.5V_1) P14.28(+1.5V_2) P14.48(+1.5V_3) R169.1 ; also on sheet 2 7
3V3_PER: C150.2 C151.2 C168.1 C169.1 C170.1 C171.1 C172.1 C173.1 C174.1 C190.2 C196.1 C197.1 C198.1 C199.1 C200.1 C201.1 C202.1 C212.2 C229.1 C230.1 L20.2 P14.2(+3.3V_1) P14.39(RSVD6) P14.41(RSVD7) P14.52(+3.3V_2) P18.2(+3.3V_1) P18.24(+3.3V_AUX) P18.39(RSVD6) P18.41(RSVD7) P18.52(+3.3V_2) R2.1 R154.1 R186.2 R187.2 R188.2 R198.2 R210.2 R215.2 R227.1 U23.8(VCC) U27.9(VCC) U33.15(VCC3) U41.3(VCCA) ; also on sheet 2 3 4 5 6 7 8
5V0_PER: C135.2 C136.2 C183.1 C209.2 C213.2 C216.2 L18.2 P14.44(LED_WLAN#) R141.1 U26.5(VCC) U28.5(VCC) U29.6(Vin) U29.7(Vin) ; also on sheet 2 4 5
+VBATA_IN: D6.ANODE FB1.2 FB2.2
GND: BH1.1(MINUS) C119.2 C130.2 C133.2 C134.2 C135.1 C136.1 C138.2 C144.2 C145.2 C146.1 C147.1 C148.2 C149.2 C150.1 C151.1 C154.2 C155.2 C158.2 C159.2 C160.1 C161.1 C162.2 C164.2 C165.2 C166.2 C167.2 C168.2 C169.2 C170.2 C171.2 C172.2 C173.2 C174.2 C175.2 C176.2 C177.2 C178.2 C179.2 C180.2 C181.2 C182.2 C183.2 C184.2 C185.2 C186.2 C187.2 C188.2 C189.2 C190.1 C196.2 C197.2 C198.2 C199.2 C200.2 C201.2 C202.2 C203.2 C208.1 C209.1 C210.1 C211.2 C212.1 C213.1 C214.2 C215.1 C216.1 C217.2 C222.1 C223.1 C228.2 C229.2 C230.2 C231.1 D7.ANODE DS1.CATHODE DS2.CATHODE J4.2(R) J4.SH1 J4.SH2 J4.SH3 J4.SH4 J5.4(GND) J5.5(SHELL_1) J5.6(SHELL_2) L22.5(GND) L22.6(GND) L23.5(GND) L23.6(GND) L24.5(GND) L24.6(GND) P13.S1(SHIELD) P13.S2(SHIELD) P14.4(GND7) P14.9(GND1) P14.15(GND2) P14.18(GND8) P14.21(GND3) P14.26(GND9) P14.27(GND4) P14.29(GND5) P14.34(GND10) P14.35(GND6) P14.37(RSVD5) P14.40(GND11) P14.50(GND12) P15.G1 P15.G2 P15.G3 P15.G4 P15.P6(VSS) P15.SH1 P15.SH2 P16.5(GND) P16.6(SHIELD1) P16.7(SHIELD2) P16.8(SHIELD3) P16.9(SHIELD4) P17.5 P17.10(BRACKET) P17.11(BRACKET) P18.4(GND7) P18.9(GND1) P18.15(GND2) P18.18(GND8) P18.21(GND3) P18.26(GND9) P18.27(GND4) P18.29(GND5) P18.34(GND10) P18.35(GND6) P18.37(RSVD5) P18.40(GND11) P18.50(GND12) P20.5(GND) P20.9(M9) P20.10(M10) P20.11(M11) P20.12(M12) P21.5(GND) P21.6(SHIELD1) P21.7(SHIELD2) P21.8(SHIELD3) P21.9(SHIELD4) Q4.4(S) Q5.1(S1) Q5.4(S2) Q6.1(S) R142.2 R143.2 R144.2 R155.2 R156.2 R158.2 R159.2 R160.2 R161.2 R170.2 R171.2 R172.2 R173.2 R174.2 R189.1 R206.2 R208.1 R212.2 R213.1 R218.2 R219.1 RN3.1(RA1) RN3.2(RB1) RN3.3(RC1) RN3.4(RD1) U13.3(GND) U14.4(GND) U14.9(PAD) U15.4(GND) U15.9(PAD) U16.4(GND) U16.9(PAD) U18.4(GND) U18.9(PAD) U19.2(GND) U20.2(GND) U21.2(GND) U22.2(GND) U23.4(GND) U26.2(GND) U27.4(GND) U28.2(GND) U29.4(GND) U33.1(EN) U33.14(GND) U41.2(GND) ; also on sheet 2 3 4 5 6 7 8
V1V8_BOOT: C157.1 U18.2(BOOT)
V1V8_COMP: C163.1 C164.1 U18.6(COMP)
V1V8_COMP_C: C163.2 R172.1
V1V8_EN: R162.2 R166.1 R168.1 U18.3(EN)
V1V8_FB: R169.2 R171.1 U18.5(FB)
V1V8_RLIM: R170.1 U18.7(RLIM)
V1V8_SW: C157.2 L21.1 U18.1(SW)
V3V3_BOOT: C141.1 U16.2(BOOT)
V3V3_COMP: C153.1 C155.1 U16.6(COMP)
V3V3_COMP_C: C153.2 R161.1
V3V3_EN: R145.2 R148.1 R150.1 U16.3(EN)
V3V3_FB: R154.2 R159.1 U16.5(FB)
V3V3_RLIM: R156.1 U16.7(RLIM)
V3V3_SW: C141.2 L20.1 U16.1(SW)
V5_BOOT: C132.1 U14.2(BOOT)
V5_COMP: C137.1 C138.1 U14.6(COMP)
V5_COMP_C: C137.2 R144.1
V5_FB: R141.2 R143.1 U14.5(FB)
V5_RLIM: R142.1 U14.7(RLIM)
V5_SW: C132.2 L18.1 U14.1(SW)
V5V0_EN: R133.2 R136.1 R140.1 U14.3(EN)
VBUS_USB_A: C210.2 C211.1 C217.1 J5.1(VBUS) R201.1 R203.1 U29.2(Vout) U29.3(Vout)
VCC_POE: C179.1 D9.ANODE P14.49(RSVD11) P14.51(RSVD12)
VCC_RTC: E9.1 ; also on sheet 3
VCC_SD: C184.1 C185.1 C186.1 C187.1 C188.1 C189.1 P15.P4(VDD) R183.1 R226.1 R227.2 RN2.5(COM1) RN2.10(COM2) U21.5(VBUS) U22.5(VBUS)
AUD_nINT: P14.8(UIM_PWR) ; also on sheet 4
CARRIER_EEPROM_WP: R189.2 U23.7(WP)
CON_UART1_RXD: U19.21(TXD) U41.1(B2)
CON_UART1_TXD: U19.20(RXD) U41.8(B1)
CP2104VPP: C203.1 U19.16(VPP)
DB9_RXD: P17.2 R190.1
DB9_TXD: P17.3 R191.1
DC_IN: D7.CATHODE FB1.1 FB2.1 J4.1(CENTRAL)
ENET2_MDC: P14.11(REFCLK-) ; also on sheet 3
ENET2_MDIO: P14.13(REFCLK+) ; also on sheet 3
ENET2_RD0: P14.17(RSVD3) ; also on sheet 3
ENET2_RD1: P14.19(RSVD4) ; also on sheet 3
ENET2_RD2: P14.23(PER_N0) ; also on sheet 3
ENET2_RD3: P14.25(PER_P0) ; also on sheet 3
ENET2_RX_CTL: P14.33(PET_P0) ; also on sheet 3
ENET2_RXC: P14.31(PET_N0) ; also on sheet 3
ENET2_TD0: P14.20(RSVD18) ; also on sheet 3
ENET2_TD1: P14.22(PERST#) ; also on sheet 3
ENET2_TD2: P14.24(+3.3V_AUX) ; also on sheet 3
ENET2_TD3: P14.36(USB_D-) ; also on sheet 3
ENET2_TX_CTL: P14.32(SMB_DATA) ; also on sheet 3
ENET2_TXC: P14.30(SMB_CLK) ; also on sheet 3
EPR_A0: R186.1 RN3.8(RA2) U23.1(A0)
EPR_A1: R187.1 RN3.7(RB2) U23.2(A1)
EPR_A2: R188.1 RN3.6(RC2) U23.3(A2)
ETH0_CT1A: C165.1 C166.1 P13.P5(CT)
ETH1_CT2A: C167.1 P13.P6(CT)
ETH1_GREEN_LED_CAT: P13.P11(LED1_C) R173.1
ETH1_LED_ACT/PHY1ADDRESS2: P13.P12(LED1_A) ; also on sheet 3
ETH1_LINK-LED_10_100: D8.1(ANODE1) R193.2 ; also on sheet 3
ETH1_LINK-LED_1000/INTSELECT: D8.2(ANODE2) ; also on sheet 3
ETH1_MDI0N: P13.P2(MDI0-) ; also on sheet 3
ETH1_MDI0P: P13.P1(MDI0+) ; also on sheet 3
ETH1_MDI1N: P13.P4(MDI1-) ; also on sheet 3
ETH1_MDI1P: P13.P3(MDI1+) ; also on sheet 3
ETH1_MDI2N: P13.P8(MDI2-) ; also on sheet 3
ETH1_MDI2P: P13.P7(MDI2+) ; also on sheet 3
ETH1_MDI3N: P13.P10(MDI3-) ; also on sheet 3
ETH1_MDI3P: P13.P9(MDI3+) ; also on sheet 3
ETH1_YELLOW_LED_AN: D8.3(CATHODE) P13.P14(LED2_A) R193.1
ETH1_YELLOW_LED_CAT: P13.P13(LED2_C) R174.1
EXTEN_GPIO_1: P14.38(USB_D+) ; also on sheet 4
EXTEN_GPIO_2: P14.42(LED_WWAN#) ; also on sheet 4
HASW_IP1: R218.1 U29.8(IP)
HOSTA_USB_DN: J5.2(D-) L23.4
HOSTA_USB_DP: J5.3(D+) L23.3
I2C3_SCL_CM: P14.14(UIM_RESET) U23.6(SCL) ; also on sheet 4 5 7 8
I2C3_SDA_CM: P14.16(UIM_VPP) U23.5(SDA) ; also on sheet 4 5 7 8
ID_VBUS_SEL: R205.2 R206.1 U26.6(SEL) U28.6(SEL)
MODEM_RST: P18.17(RSVD3) ; also on sheet 4
mPCIE_USB_DN: L22.4 P18.36(USB_D-)
mPCIE_USB_DP: L22.3 P18.38(USB_D+)
mux_PCIe_USB_DN: L22.1 ; also on sheet 2
mux_PCIe_USB_DP: L22.2 ; also on sheet 2
MUX_USB1_DN: L23.1 U27.7(HSD1-)
MUX_USB1_DP: L23.2 U27.1(HSD1+)
MUX_USB3_SEL: Q6.2(G) R219.2 R225.2
PMIC_ON_REQ: Q5.5(G2) ; also on sheet 3
PMIC_ON_REQn: Q5.2(G1) Q5.3(D2) R139.2
PMIC_STBY_REQ: Q4.5(G) ; also on sheet 3
PWR_CTRL: R133.1 R138.2 R145.1 R162.1 U13.4(Y)
PWR_CTRL_IN: Q4.3(D) Q5.6(D1) R137.2 R138.1 U13.2(A)
RS232_PU: R2.2 U33.12(FORCEON) U33.16(FORCEOFF)
RS232_RXD: R190.2 U33.8(R1IN)
RS232_TXD: R191.2 U33.13(T1OUT)
RS232DB_LED: DS2.ANODE R185.2
RS_C1+: C227.2 U33.2(C1+)
RS_C1-: C227.1 U33.4(C1-)
RS_C2+: C118.1 U33.5(C2+)
RS_C2-: C118.2 U33.6(C2-)
RS_V+: C228.1 U33.3(V+)
RS_V-: C119.1 U33.7(V-)
SAI1_RXD0: P14.7(CLKREQ#) ; also on sheet 3
SAI1_TXC/CAN1_RX: P14.1(WAKE#) ; also on sheet 3
SD2_CLK: R181.2 ; also on sheet 3
SD2_CMD: R182.2 ; also on sheet 3
SD2_DATA0: R177.2 ; also on sheet 3
SD2_DATA1: R178.2 ; also on sheet 3
SD2_DATA2: R179.2 ; also on sheet 3
SD2_DATA3: R180.2 ; also on sheet 3
SD2_nCD: P15.P9(CD#) R183.2 ; also on sheet 3
SDCARD_CLK: P15.P5(CLK) R181.1 RN2.7(R6) U21.3(IO2)
SDCARD_CMD: P15.P3(CMD) R182.1 RN2.8(R7) U22.6(IO4)
SDCARD_DAT0: P15.P7(DAT0) R177.1 RN2.1(R1) U21.1(IO1)
SDCARD_DAT1: P15.P8(DAT1) R178.1 RN2.2(R2) U21.6(IO4)
SDCARD_DAT2: P15.P1(DAT2) R179.1 RN2.3(R3) U22.1(IO1)
SDCARD_DAT3: P15.P2(DAT3) R180.1 RN2.4(R4) U22.4(IO3)
SERIAL_VBUSIN: C182.1 P16.1(VBUS) R185.1 U19.7(REGIN) U19.8(VBUS) U20.4(IO3)
SIM1_CLK: P18.12(UIM_CLK) P20.3(CLK)
SIM1_IO: P18.10(UIM_DATA) P20.7(IO)
SIM1_RST: P18.14(UIM_RESET) P20.2(RST)
SIM1_VCC: C208.2 P18.8(UIM_PWR) P20.1(VCC)
SIM1_VPP: P18.16(UIM_VPP) P20.6(VPP)
SW_SAI1_TXD0/CAN1_TX: P14.5(RSVD2) ; also on sheet 3
SW_SAI1_TXFS: P14.3(RSVD1) ; also on sheet 3
SW_UART1_TXD: U41.5(A1) ; also on sheet 3
SW_UART2_TXD: U33.11(T1IN) ; also on sheet 3
U28_IN0: R213.2 U28.3(B0)
U28_OUT: R211.1 U28.4(A)
U29_EN: Q6.6(D) R215.1 U29.5(EN)
U31_IN0: R203.2 U26.3(B0)
U31_IN1: R202.2 U26.1(B1)
U31_OUT: R204.1 U26.4(A)
U32_OEL: R208.2 U27.8(\\~{O}E)
U41_OE: R198.1 U41.6(OE)
UART1_RXD: U41.4(A2) ; also on sheet 3
UART2_R2OUT: R192.2 U33.9(R1OUT)
UART2_RXD: R192.1 ; also on sheet 3
USB1_DN: U27.5(D-) ; also on sheet 3
USB1_DP: U27.3(D+) ; also on sheet 3
USB1_ID: R211.2 ; also on sheet 3
USB1_SEL: R207.1 U27.10(SEL)
USB1_VBUS_3V3: R201.2 R204.2 ; also on sheet 3
USB1SEL: R207.2 R209.1 R212.1
USB_SDM_DN: L24.1 U27.6(HSD2-)
USB_SDM_DP: L24.2 U27.2(HSD2+)
USBSD_VBUS: C214.1 C215.2 P21.1(VBUS) R202.1 R205.1 R209.2 R225.1
USBSDM_DN: L24.4 P21.2(D-)
USBSDM_DP: L24.3 P21.3(D+)
USBSERIAL_3V45: C180.1 C181.1 C231.2 R184.2 U19.5(VIO) U19.6(VDD) U41.7(VCCB)
USBSERIAL_DN: P16.2(D-) U19.4(DN) U20.6(IO4)
USBSERIAL_DP: P16.3(D+) U19.3(DP) U20.1(IO1)
USBSERIAL_nRST: R184.1 U19.9(RST#)
uUSB_ID: P21.4(ID) R210.1 U28.1(B1)
V_COIN: BH1.2(PLUS) C162.1 R167.1
V_SOM: C130.1 C146.2 C147.2 E8.1 R1.2 R136.2 R137.1 R139.1 R148.2 R164.1 R166.2 U13.5(VCC) ; also on sheet 3 6
V_SOM_L: C222.2 C223.2 E8.2 L19.2 R1.1 R153.1
VCOIN: E9.2 R167.2
VDC_IN: C133.1 C134.1 C144.1 C145.1 C148.1 C149.1 C158.1 C159.1 D6.CATHODE D9.CATHODE R140.2 R149.2 R150.2 R168.2 U14.8(VIN) U15.8(VIN) U16.8(VIN) U18.8(VIN)
VSD_3V3: R226.2 ; also on sheet 3
VSOM_BOOT: C140.1 U15.2(BOOT)
VSOM_COMP: C152.1 C154.1 U15.6(COMP)
VSOM_COMP_C: C152.2 R160.1
VSOM_EN: R149.1 U15.3(EN)
VSOM_FB: R153.2 R158.1 U15.5(FB)
VSOM_LED: DS1.ANODE R164.2
VSOM_RLIM: R155.1 U15.7(RLIM)
VSOM_SW: C140.2 L19.1 U15.1(SW)

Not connected (* = marked no-connect by the designer): P14 10(UIM_DATA)* 12(UIM_CLK)* 43(RSVD8)* 45(RSVD9)* 46(LED_WPAN#)* 47(RSVD10)*; P16 4(ID)*; P17 1* 4* 6* 7* 8* 9*; P18 1(WAKE#)* 3(RSVD1)* 5(RSVD2)* 6(+1.5V_1)* 7(CLKREQ#)* 11(REFCLK-)* 13(REFCLK+)* 19(RSVD4)* 20(RSVD18)* 22(PERST#)* 23(PER_N0)* 25(PER_P0)* 28(+1.5V_2)* 30(SMB_CLK)* 31(PET_N0)* 32(SMB_DATA)* 33(PET_P0)* 42(LED_WWAN#)* 43(RSVD8)* 44(LED_WLAN#)* 45(RSVD9)* 46(LED_WPAN#)* 47(RSVD10)* 48(+1.5V_3)* 49(RSVD11)* 51(RSVD12)*; P20 4(RSVD4)* 8(RSVD8)*; RN2 6(R5)* 9(R8)*; RN3 5(RD2)*; U19 1(RI)* 10(NC)* 11(GPIO3)* 12(GPIO2)* 13(GPIO1)* 14(GPIO0)* 15(SUSPEND#)* 17(SUSPEND)* 18(CTS)* 19(RTS)* 22(DSR)* 23(DTR)* 24(DCD)*; U20 3(IO2)* 5(VBUS)*; U21 4(IO3)*; U22 3(IO2)*; U29 1(FLG)*; U33 10(INVALID)*

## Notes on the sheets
sheet 9
- DC input
- V_SOM (3A)
- Vout=3.7V
  Iout max = 3A
- Current measure
- Vin 10V-36V
  Imax (vin=10V) =3.31A
- DNP
- Vout=0.8*(1+64.9/17.8)=3.72V
- RLIM = 100k => ~4A
- VCC_3V3
- VCC_1V8
- Vout=0.8*(1+56.2/17.8)=3.33V
- Vout=0.8*(1+22.1/17.8)=1.79V
- Vout=3.3V
  Iout max = 3A
- Vout=1.8V
  Iout max = 3A
- RLIM = 100k => ~4A
- RLIM = 100k => ~4A
- DNP
- DNP
- VCC_5V
- PWR_CTRLn
- RTC battery
- Vout=5V
  Iout max = 3A
- Vout=0.8*(1+64.9/12.4)=4.987V
- DNP
- DNP
- RLIM = 100k => ~4A
- DNP
sheet 10
- Ethernet connector
- 100 Ohm
- 100 Ohm
- 100 Ohm
- 100 Ohm
- DNP
- Expansion connector
- For 2nd Ethernet and RGMII
- I2S for CODEC or
  PHY_RST,INT,WOL ..
sheet 11
- Serial Console
- USB-to-Serial
- UART LEVEL SHIFTER
- Prevents power draining to board when only
  usb cable is connected
- DEBUG PORT
  (microUSB2.0 Type B)
  UART over USB
- A53 core debug
- USB console
  connection
  indicator
- In
- Out
- DNP
- RS232
- Micro-SD (bootable)
- DNP
- RS-232
- DNP
- M33 core debug
- miniPCIe and SIM
- EEPROM
- DNP
- DNP
- 3.3V x 2mA = 6.6mW
- I2C slave address: 0x54..0x57
sheet 12
- USB1
- Host with mux for SDP mode
- DNP
- NOTE: USB1 multiplexing is controlled by presence of VBUS on connector P21
- 90 ohm
- # 90-Ohm differential pairs
- # 90-Ohm diff pairs
- Assembly ACAP to L23
- 1.05A LIMIT
- Serial Download mode
  (microUSB2.0 Type B)
- DNP
- Mux for USB1 ID and VBUS
